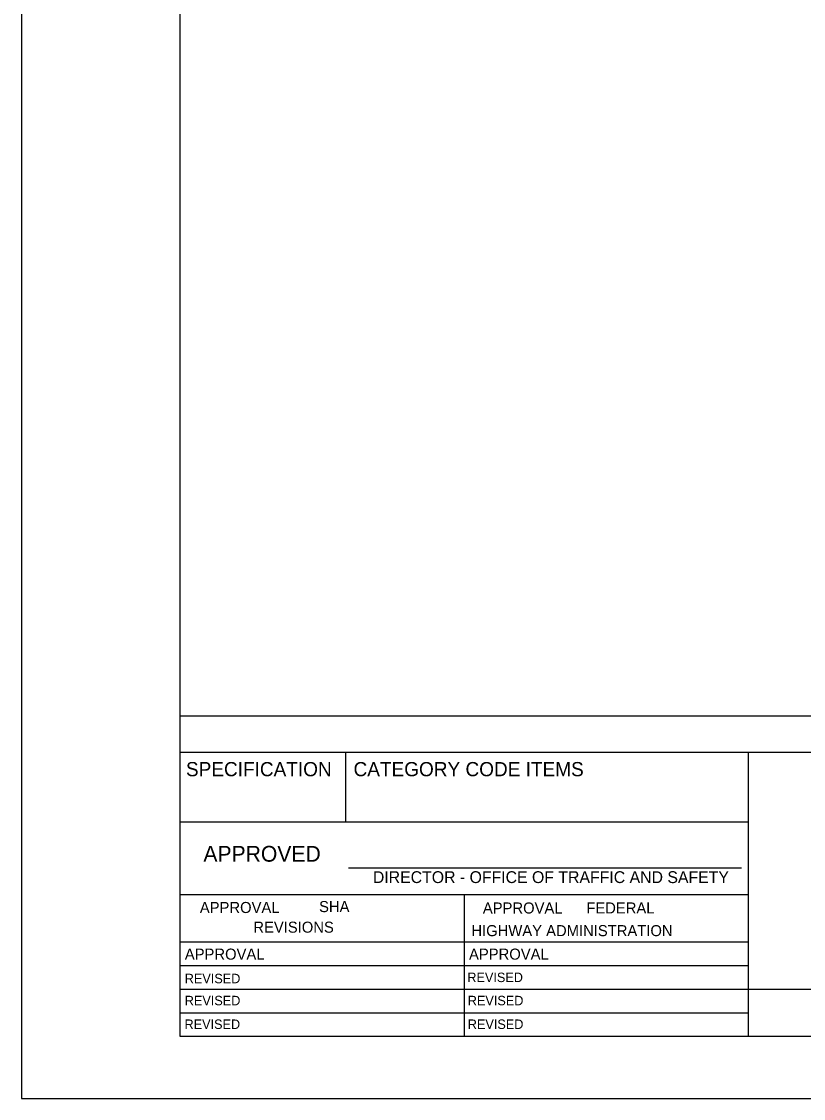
# Model space of a CAD drawing. Extents: x -0.5 to 19.9, y 5.2 to 17.3.
# Drawn here: x 11.44 to 15.43, y 5.67 to 11.17 of the extents above; entities that cross this region are included whole.
import ezdxf

# ---------------------------------------------------------------- set-up
doc = ezdxf.new("R2010")
doc.units = 0
for name, color, linetype in [('BORD-LINE', 7, 'Continuous'), ('TTLB-TEXT', 7, 'Continuous'), ('USER-CLIP', 7, 'Continuous')]:
    doc.layers.add(name, color=color, linetype=linetype)

msp = doc.modelspace()

# ---------------------------------------------------------------- linework, layer by layer
at = {"layer": 'BORD-LINE'}
for p, q in [((19.6208, 7.6193), (12.2466, 7.6193)), ((15.1479, 7.4352), (12.2466, 7.4352)), ((13.0928, 7.0805), (13.0928, 7.4352)), ((15.1479, 5.9844), (15.1479, 7.4352)), ((19.6208, 7.4352), (15.1479, 7.4352)), ((12.2466, 7.0805), (15.1479, 7.0805)), ((13.1058, 6.8454), (15.1127, 6.8454)), ((12.2466, 6.7098), (13.0928, 6.7098)), ((12.2466, 5.9844), (12.2466, 6.7098)), ((12.2466, 6.7098), (15.1479, 6.7098)), ((13.6972, 6.7098), (13.6972, 5.9844)), ((12.2466, 6.468), (15.1479, 6.468)), ((12.2466, 6.3471), (15.1479, 6.3471)), ((12.2466, 6.2262), (15.1479, 6.2262)), ((15.1479, 6.2262), (19.6208, 6.2262)), ((12.2466, 6.1053), (15.1479, 6.1053)), ((13.0928, 6.1053), (15.1479, 6.1053))]:
    msp.add_line(p, q, dxfattribs=at)
msp.add_lwpolyline([(12.2466, 16.3375), (19.6208, 16.3375), (19.6208, 5.9844), (12.2466, 5.9844)], close=True, dxfattribs=at)
at = {"layer": 'USER-CLIP'}
msp.add_lwpolyline([(19.9377, 16.6675), (11.4377, 16.6675), (11.4377, 5.6675), (19.9377, 5.6675)], close=True, dxfattribs=at)

# ---------------------------------------------------------------- texts
at = {"layer": 'TTLB-TEXT'}
for s, height, p in [('SPECIFICATION', 0.07254, (12.2768, 7.3131)), ('CATEGORY CODE ITEMS ', 0.07254, (13.1321, 7.3131)), ('APPROVED', 0.0806, (12.3658, 6.8768)), ('DIRECTOR - OFFICE OF TRAFFIC AND SAFETY', 0.0604, (13.2308, 6.7676)), ('APPROVAL', 0.05642, (12.3476, 6.6146)), ('SHA', 0.05642, (12.9562, 6.6193)), ('APPROVAL', 0.05642, (13.7921, 6.6121)), ('FEDERAL', 0.05642, (14.3202, 6.6122)), ('REVISIONS', 0.05642, (12.6207, 6.5141)), ('HIGHWAY ADMINISTRATION', 0.05642, (13.7336, 6.4964)), ('APPROVAL', 0.05642, (12.271, 6.3764)), ('APPROVAL', 0.05642, (13.7216, 6.3764)), ('REVISED', 0.04836, (12.2707, 6.2559)), ('REVISED', 0.04836, (13.7129, 6.2618)), ('REVISED', 0.04836, (12.2707, 6.1433)), ('REVISED', 0.04836, (13.7152, 6.1433)), ('REVISED', 0.04836, (12.2694, 6.0225)), ('REVISED', 0.04836, (13.7152, 6.0225))]:
    msp.add_text(s, height=height, dxfattribs=at).set_placement(p)

doc.saveas('drawing.dxf')
